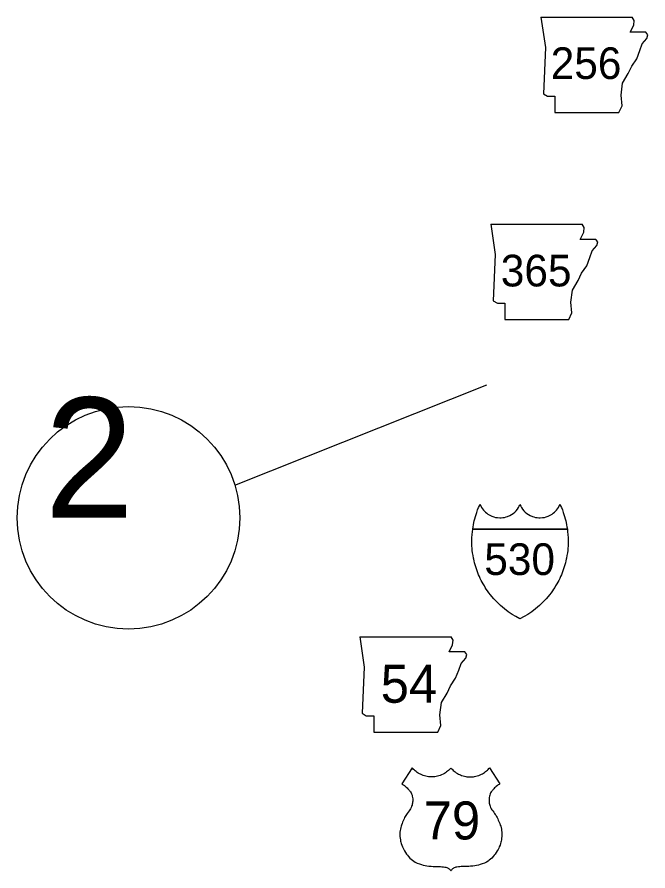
# Model space of a CAD drawing. Extents: x -819161 to 80911, y -6604 to 768454.
# Drawn here: x 44180 to 45231, y -6569 to -5145 of the extents above; entities that cross this region are included whole.
import ezdxf

# ---------------------------------------------------------------- set-up
doc = ezdxf.new("R2010")
doc.units = 0
for name, color, linetype in [('21', 7, 'Continuous'), ('22', 7, 'Continuous'), ('23', 7, 'Continuous'), ('DSN_DRFT_Common-Line', 7, 'Continuous'), ('Level 23', 7, 'Continuous')]:
    doc.layers.add(name, color=color, linetype=linetype)

msp = doc.modelspace()

# ---------------------------------------------------------------- linework, layer by layer
at = {"layer": '21'}
for p, q in [((45052.2, -5145.1), (45059.8, -5195.8)), ((45207.8, -5151), (45204.3, -5145.1)), ((45207, -5158.6), (45207.8, -5151)), ((45201, -5170.4), (45207, -5158.6)), ((45227.3, -5170.4), (45201, -5170.4)), ((45221.3, -5189.9), (45228.9, -5180.6)), ((45230.6, -5174.7), (45227.3, -5170.4)), ((45228.9, -5180.6), (45230.6, -5174.7)), ((45217.1, -5200.9), (45221.3, -5189.9)), ((45059.8, -5195.8), (45056.4, -5272.8)), ((45212, -5214.4), (45217.1, -5200.9)), ((45203.6, -5227.1), (45212, -5214.4)), ((45197.6, -5238.9), (45203.6, -5227.1)), ((45188.3, -5255), (45197.6, -5238.9)), ((45185.8, -5275.3), (45188.3, -5255)), ((45056.4, -5272.8), (45063.1, -5277)), ((45063.1, -5277), (45075.8, -5277)), ((45075.8, -5277), (45075.8, -5304.1)), ((45187.5, -5293.1), (45185.8, -5275.3)), ((45182.4, -5304.1), (45187.5, -5293.1)), ((45075.8, -5304.1), (45182.4, -5304.1)), ((44968.8, -5490.2), (44976.4, -5540.9)), ((45124.4, -5496.1), (45120.9, -5490.3)), ((45117.7, -5515.6), (45123.6, -5503.7)), ((45123.6, -5503.7), (45124.4, -5496.1)), ((45143.9, -5515.6), (45117.7, -5515.6)), ((45147.3, -5519.8), (45143.9, -5515.6)), ((45145.6, -5525.7), (45147.3, -5519.8)), ((45133.7, -5546), (45138, -5535)), ((45138, -5535), (45145.6, -5525.7)), ((44976.4, -5540.9), (44973, -5617.9)), ((45128.6, -5559.5), (45133.7, -5546)), ((45120.2, -5572.2), (45128.6, -5559.5)), ((45114.3, -5584.1), (45120.2, -5572.2)), ((45105, -5600.1), (45114.3, -5584.1)), ((45102.4, -5620.4), (45105, -5600.1)), ((44973, -5617.9), (44979.8, -5622.1)), ((44979.8, -5622.1), (44992.5, -5622.1)), ((44992.5, -5622.1), (44992.5, -5649.2)), ((45104.1, -5638.2), (45102.4, -5620.4)), ((44992.5, -5649.2), (45099, -5649.2)), ((45099, -5649.2), (45104.1, -5638.2)), ((44750.4, -6178.1), (44758, -6228.8)), ((44899.3, -6203.4), (44905.2, -6191.6)), ((44906.1, -6184), (44902.6, -6178.1)), ((44905.2, -6191.6), (44906.1, -6184)), ((44925.5, -6203.4), (44899.3, -6203.4)), ((44928.9, -6207.7), (44925.5, -6203.4)), ((44919.6, -6222.9), (44927.2, -6213.6)), ((44927.2, -6213.6), (44928.9, -6207.7)), ((44758, -6228.8), (44754.7, -6305.8)), ((44910.3, -6247.4), (44915.4, -6233.9)), ((44915.4, -6233.9), (44919.6, -6222.9)), ((44901.8, -6260.1), (44910.3, -6247.4)), ((44895.9, -6272), (44901.8, -6260.1)), ((44886.6, -6288), (44895.9, -6272)), ((44884.1, -6308.3), (44886.6, -6288)), ((44754.7, -6305.8), (44761.4, -6310)), ((44761.4, -6310), (44774.1, -6310)), ((44774.1, -6310), (44774.1, -6337.1)), ((44885.8, -6326.1), (44884.1, -6308.3)), ((44880.7, -6337.1), (44885.8, -6326.1)), ((44774.1, -6337.1), (44880.7, -6337.1))]:
    msp.add_line(p, q, dxfattribs=at)
for points in [[(45052.2, -5145.1), (45204.3, -5145.1)], [(44968.8, -5490.2), (45120.9, -5490.3)], [(44750.4, -6178.1), (44902.6, -6178.1)]]:
    msp.add_lwpolyline(points, dxfattribs=at)
at = {"layer": '22'}
for points in [[(44902.3, -6397), (44901, -6398.4), (44899.8, -6399.7), (44898.3, -6401.1), (44896.8, -6402.4), (44895.3, -6403.5), (44893.5, -6404.8), (44891.6, -6406), (44889.4, -6407.2), (44886.6, -6408.5), (44884.4, -6409.4), (44882, -6410.1), (44879.8, -6410.7), (44877.7, -6411.1), (44875.5, -6411.5), (44873.6, -6411.7), (44870.8, -6411.8), (44868.6, -6411.8), (44866.7, -6411.7), (44864.9, -6411.5), (44863, -6411.2), (44860.7, -6410.7), (44858.5, -6410.2), (44855.9, -6409.3), (44853.7, -6408.4), (44851.6, -6407.5), (44849.8, -6406.5), (44848.1, -6405.5), (44846.2, -6404.3), (44844.4, -6403), (44842.9, -6401.7), (44841.6, -6400.6), (44840.3, -6399.3), (44839, -6398), (44838, -6396.8), (44820.7, -6423.6), (44821.9, -6424.3), (44823.4, -6425.3), (44824.8, -6426.3), (44826.7, -6427.7), (44828.1, -6429), (44829.5, -6430.2), (44830.8, -6431.6), (44832.2, -6433.1), (44833.2, -6434.3), (44834.1, -6435.6), (44835.1, -6436.9), (44836.1, -6438.4), (44837, -6440.1), (44837.6, -6442.2), (44838.1, -6444.2), (44838.5, -6446.4), (44838.7, -6448.5), (44838.8, -6450.5), (44838.7, -6452.3), (44838.6, -6453.8), (44838.4, -6455.6), (44838, -6457.4), (44837.6, -6459.2), (44837, -6460.8), (44836.3, -6462.7), (44835.2, -6465), (44834, -6466.9), (44832.7, -6468.6), (44831, -6470.7), (44829.6, -6472.6), (44828.3, -6474.5), (44827.1, -6476.4), (44826.1, -6478.1), (44825.3, -6479.7), (44824.3, -6481.5), (44823.2, -6483.7), (44822.3, -6485.9), (44821.7, -6487.4), (44820.9, -6489.5), (44820, -6492), (44819.4, -6494), (44818.7, -6496.3), (44818.2, -6498.9), (44817.8, -6501.3), (44817.5, -6503.7), (44817.3, -6506.4), (44817.3, -6508.9), (44817.4, -6511.3), (44817.7, -6514.2), (44818.2, -6516.9), (44818.6, -6519), (44819.1, -6520.8), (44819.7, -6522.8), (44820.5, -6525.4), (44821.6, -6528.4), (44822.6, -6530.7), (44823.8, -6533.1), (44825, -6535.3), (44826.6, -6538), (44828.3, -6540.4), (44830, -6542.5), (44831.8, -6544.6), (44834.2, -6547.1), (44836.2, -6549), (44838.3, -6550.8)], [(44902.3, -6397), (44903.7, -6398.4), (44904.9, -6399.7), (44906.3, -6401.1), (44907.9, -6402.4), (44909.4, -6403.5), (44911.2, -6404.8), (44913.1, -6406), (44915.3, -6407.2), (44918.1, -6408.5), (44920.3, -6409.4), (44922.7, -6410.1), (44924.9, -6410.7), (44927, -6411.1), (44929.1, -6411.5), (44931.1, -6411.7), (44933.8, -6411.8), (44936.1, -6411.8), (44938, -6411.7), (44939.8, -6411.5), (44941.7, -6411.2), (44944, -6410.7), (44946.2, -6410.2), (44948.8, -6409.3), (44951, -6408.4), (44953.1, -6407.5), (44954.9, -6406.5), (44956.6, -6405.5), (44958.5, -6404.3), (44960.3, -6403), (44961.8, -6401.7), (44963.1, -6400.6), (44964.4, -6399.3), (44965.7, -6398), (44966.7, -6396.8), (44984, -6423.6), (44982.8, -6424.3), (44981.3, -6425.3), (44979.9, -6426.3), (44978, -6427.7), (44976.5, -6429), (44975.2, -6430.2), (44973.9, -6431.6), (44972.5, -6433.1), (44971.5, -6434.3), (44970.6, -6435.6), (44969.6, -6436.9), (44968.6, -6438.4), (44967.7, -6440.1), (44967.1, -6442.2), (44966.6, -6444.2), (44966.2, -6446.4), (44966, -6448.5), (44965.9, -6450.5), (44965.9, -6452.3), (44966.1, -6453.8), (44966.3, -6455.6), (44966.6, -6457.4), (44967.1, -6459.2), (44967.7, -6460.8), (44968.4, -6462.7), (44969.5, -6465), (44970.6, -6466.9), (44972, -6468.6), (44973.7, -6470.7), (44975.1, -6472.6), (44976.4, -6474.5), (44977.6, -6476.4), (44978.6, -6478.1), (44979.4, -6479.7), (44980.4, -6481.5), (44981.4, -6483.7), (44982.4, -6485.9), (44983, -6487.4), (44983.8, -6489.5), (44984.6, -6492), (44985.3, -6494), (44985.9, -6496.3), (44986.5, -6498.9), (44986.9, -6501.3), (44987.2, -6503.7), (44987.3, -6506.4), (44987.4, -6508.9), (44987.2, -6511.3), (44986.9, -6514.2), (44986.5, -6516.9), (44986.1, -6519), (44985.6, -6520.8), (44985, -6522.8), (44984.2, -6525.4), (44983, -6528.4), (44982.1, -6530.7), (44980.9, -6533.1), (44979.7, -6535.3), (44978, -6538), (44976.4, -6540.4), (44974.7, -6542.5), (44972.9, -6544.6), (44970.5, -6547.1), (44968.4, -6549), (44966.4, -6550.8)], [(44838.3, -6550.8), (44840.5, -6552.4), (44843.1, -6554.1), (44846.4, -6555.6), (44850.2, -6557), (44853.3, -6558.1), (44856.2, -6558.8), (44859.3, -6559.6), (44862.3, -6560.1), (44865.5, -6560.6), (44869.6, -6560.9), (44872.7, -6561), (44875.3, -6561), (44877.9, -6561), (44880.5, -6561.1), (44882.9, -6561.2), (44885.1, -6561.4), (44887.2, -6561.6), (44889.9, -6561.8), (44892.5, -6562.2), (44894.1, -6562.4), (44895.4, -6562.6), (44896.9, -6563.3), (44897.8, -6563.8), (44898.6, -6564.3), (44899.7, -6565.2), (44900.7, -6566.2), (44901.6, -6567.3), (44902.3, -6568.6)], [(44966.4, -6550.8), (44964.2, -6552.4), (44961.6, -6554.1), (44958.3, -6555.6), (44954.5, -6557), (44951.3, -6558.1), (44948.5, -6558.8), (44945.3, -6559.6), (44942.4, -6560.1), (44939.1, -6560.6), (44935.1, -6560.9), (44932, -6561), (44929.4, -6561), (44926.8, -6561), (44924.2, -6561.1), (44921.8, -6561.2), (44919.6, -6561.4), (44917.5, -6561.6), (44914.8, -6561.8), (44912.2, -6562.2), (44910.6, -6562.4), (44909.3, -6562.6), (44907.7, -6563.3), (44906.8, -6563.8), (44906.1, -6564.3), (44905, -6565.2), (44903.9, -6566.2), (44903.1, -6567.3), (44902.3, -6568.6)]]:
    msp.add_lwpolyline(points, dxfattribs=at)
at = {"layer": '23'}
for points in [[(44938.7, -5998.9), (44939.2, -5995.1), (44939.8, -5991.8), (44940.7, -5987.5), (44941.4, -5984.7), (44942.2, -5981.4), (44943.3, -5977.5), (44944.3, -5974.2), (44945.4, -5970.8), (44946.9, -5966.7), (44948.5, -5962.8), (44949.8, -5959.8), (44950.8, -5957.4), (44952, -5960), (44953.4, -5962.4), (44954.8, -5964.7), (44956.7, -5967.1), (44958.3, -5968.8), (44960.1, -5970.6), (44962, -5972.2), (44964.1, -5973.7), (44967.4, -5975.7), (44970.7, -5977.3), (44973.8, -5978.3), (44976.8, -5979.1), (44980, -5979.6), (44983.7, -5979.9), (44986.2, -5979.8), (44989, -5979.6), (44991.5, -5979.1), (44994.2, -5978.5), (44996.9, -5977.6), (45000.6, -5976), (45003.1, -5974.6), (45006, -5972.6), (45008.8, -5970.2), (45010.9, -5968.1), (45013.2, -5965.3), (45015.1, -5962.4), (45016.3, -5960.4), (45017.5, -5957.7)], [(45017.5, -5957.7), (45018.7, -5960.4), (45019.9, -5962.4), (45021.8, -5965.3), (45024.1, -5968.1), (45026.2, -5970.2), (45029, -5972.6), (45031.9, -5974.6), (45034.4, -5976), (45038.1, -5977.6), (45040.8, -5978.5), (45043.5, -5979.1), (45046, -5979.6), (45048.8, -5979.8), (45051.3, -5979.9), (45055, -5979.6), (45058.3, -5979.1), (45061.3, -5978.3), (45064.3, -5977.3), (45067.7, -5975.7), (45070.9, -5973.7), (45073, -5972.2), (45074.9, -5970.6), (45076.8, -5968.8), (45078.3, -5967.1), (45080.2, -5964.7), (45081.7, -5962.4), (45083, -5960), (45084.2, -5957.4), (45085.2, -5959.8), (45086.5, -5962.8), (45088.1, -5966.7), (45089.6, -5970.8), (45090.7, -5974.2), (45091.7, -5977.5), (45092.8, -5981.4), (45093.7, -5984.7), (45094.3, -5987.5), (45095.2, -5991.8), (45095.8, -5995.1), (45096.4, -5998.9)], [(45017.5, -6148.3), (45010.6, -6144.6), (45004.5, -6140.9), (44997.8, -6136.4), (44991.6, -6131.7), (44984.8, -6125.9), (44982.2, -6123.5), (44979.3, -6120.7), (44976.6, -6117.9), (44973.7, -6114.7), (44970.8, -6111.3), (44968.4, -6108.4), (44965.8, -6105), (44963.4, -6101.7), (44961.4, -6098.7), (44959.6, -6095.9), (44958.1, -6093.5), (44956.1, -6090.1), (44954.6, -6087.4), (44952.9, -6084.1), (44951.2, -6080.8), (44949.8, -6077.7), (44948.5, -6074.7), (44947.2, -6071.4), (44946, -6068.3), (44944.8, -6065.1), (44943.7, -6061.7), (44942.7, -6058.2), (44941.8, -6054.9), (44941, -6051.8), (44940.4, -6049), (44939.9, -6046.9), (44939.2, -6042.9), (44938.5, -6038.3), (44938, -6034.4), (44937.6, -6030.4), (44937.4, -6027.1), (44937.3, -6022.9), (44937.2, -6019), (44937.3, -6014.6), (44937.4, -6011.8), (44937.6, -6009.2), (44937.7, -6007.5), (44938.1, -6003.3), (44938.7, -5998.9)], [(45096.4, -5998.9), (44938.7, -5998.9)], [(44938.7, -5998.9), (45096.4, -5998.9)], [(45096.4, -5998.9), (45096.9, -6003.3), (45097.3, -6007.5), (45097.4, -6009.2), (45097.6, -6011.8), (45097.7, -6014.6), (45097.8, -6019), (45097.7, -6022.9), (45097.6, -6027.1), (45097.4, -6030.4), (45097, -6034.4), (45096.5, -6038.3), (45095.8, -6042.9), (45095.1, -6046.9), (45094.6, -6049), (45094, -6051.8), (45093.2, -6054.9), (45092.3, -6058.2), (45091.3, -6061.7), (45090.2, -6065.1), (45089, -6068.3), (45087.9, -6071.4), (45086.5, -6074.7), (45085.2, -6077.7), (45083.8, -6080.8), (45082.1, -6084.1), (45080.4, -6087.4), (45078.9, -6090.1), (45076.9, -6093.5), (45075.4, -6095.9), (45073.6, -6098.7), (45071.6, -6101.7), (45069.2, -6105), (45066.6, -6108.4), (45064.2, -6111.3), (45061.3, -6114.7), (45058.4, -6117.9), (45055.7, -6120.7), (45052.8, -6123.5), (45050.2, -6125.9), (45043.4, -6131.7), (45037.2, -6136.4), (45030.5, -6140.9), (45024.4, -6144.6), (45017.5, -6148.3)]]:
    msp.add_lwpolyline(points, dxfattribs=at)
at = {"layer": 'DSN_DRFT_Common-Line'}
msp.add_lwpolyline([(44542.5, -5925.7), (44962.1, -5758.1)], dxfattribs=at)
msp.add_circle((44365.1, -5979.8), 185.5, dxfattribs=at)

# ---------------------------------------------------------------- texts
at = {"layer": '21'}
for s, height, p in [('256', 52.8, (45068.7, -5248.3)), ('365', 52.8, (44985.5, -5594.1)), ('54', 63.36, (44785.4, -6288.2))]:
    msp.add_text(s, height=height, dxfattribs=at).set_placement(p)
at = {"layer": '22'}
msp.add_text('79', height=63.36, dxfattribs=at).set_placement((44856.9, -6516.1))
at = {"layer": 'DSN_DRFT_Common-Line'}
msp.add_text('2', height=200.4, dxfattribs=at).set_placement((44225.2, -5979.8))
at = {"layer": 'Level 23'}
msp.add_text('530', height=52.8, dxfattribs=at).set_placement((44958, -6075.2))

doc.saveas('drawing.dxf')
